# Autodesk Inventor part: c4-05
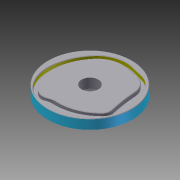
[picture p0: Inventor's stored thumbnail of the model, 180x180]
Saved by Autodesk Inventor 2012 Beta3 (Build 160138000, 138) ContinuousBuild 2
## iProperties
Created: 2010-11
Part Number: c4-05
Material: Default
Document SubType Name: Modeling
Designer: Beta-8540w
Density: 1 g/cm^3
Author: Beta-8540w
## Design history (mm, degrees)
sketch "Sketch1"
  geometry: L1 (0, 0)-(-60.5, 0); C1 r 87.5 at (0, 0); A1 r 101.47 centre (33.949, -15.027) between (-42.269, 51.956) and (-67.369, -9.495); A2 r 54.326 centre (-1.462, 16.094) between (13.023, 68.453) and (-42.269, 51.956); A3 r 616.928 centre (177.52, 663.047) between (13.023, 68.453) and (36.513, 62.449); A4 r 31.238 centre (29.374, 32.038) between (60.537, 34.197) and (36.513, 62.449); A5 r 355.938 centre (415.623, 58.803) between (60.537, 34.197) and (69.16, -22.773); A6 r 16.738 centre (52.867, -26.609) between (64.865, -38.281) and (69.16, -22.773); A7 r 90.559 centre (-0.047, 24.866) between (-4.787, -65.569) and (64.865, -38.281); A8 r 30.864 centre (-6.403, -96.391) between (-4.787, -65.569) and (-18.706, -68.085); A9 r 23.983 centre (-28.267, -46.091) between (-43.807, -64.357) and (-18.706, -68.085); A10 r 67.218 centre (-0.251, -13.16) between (-67.369, -9.495) and (-43.807, -64.357); A11 r 609.928 centre (177.52, 663.047) between (14.89, 75.2) and (38.113, 69.264); A12 r 61.326 centre (-1.462, 16.094) between (14.89, 75.2) and (-47.527, 56.577); A13 r 108.47 centre (33.949, -15.027) between (-47.527, 56.577) and (-74.359, -9.113); A14 r 74.218 centre (-0.251, -13.16) between (-74.359, -9.113) and (-48.342, -69.689); A15 r 30.983 centre (-28.267, -46.091) between (-48.342, -69.689) and (-15.916, -74.505); A16 r 23.864 centre (-6.403, -96.391) between (-5.154, -72.56) and (-15.916, -74.505); A17 r 97.559 centre (-0.047, 24.866) between (-5.154, -72.56) and (69.882, -43.162); A18 r 23.738 centre (52.867, -26.609) between (69.882, -43.162) and (75.973, -21.169); A19 r 348.938 centre (415.623, 58.803) between (67.52, 34.681) and (75.973, -21.169); A20 r 38.238 centre (29.374, 32.038) between (67.52, 34.681) and (38.113, 69.264); 1 further point
  constraints: 40 point on circle, 21 centre point, 10 tangent, 2 coincident, 2 end point, 1 horizontal, 1 horizontal alignment, 11 other
  dimensions: "d19" = 175 diameter of C1; "d23" = 27 dimension on C1; "d24" = 7 radial gap between concentric circles of A20 A4
sketch "Sketch2"
  geometry: C1 r 17.5 at (0, 0); C2 r 87.5 at (0, 0); 1 further point
  constraints: 2 centre point, 2 coincident
  dimensions: "d13" = 35 diameter of C1; "d14" = 175 diameter of C2
extrude "Extrusion2" new body sketch "Sketch2" distance "d15" = 20; taper "d16" = 0 deg
extrude "Extrusion3" cut sketch "Sketch1" distance "d17" = 8; taper "d18" = 0 deg
chamfer "Chamfer1" distance "d20" = 1; stored, may be unused: second distance "d21" = 2, angle "d22" = 45 deg
body "Solid2"
